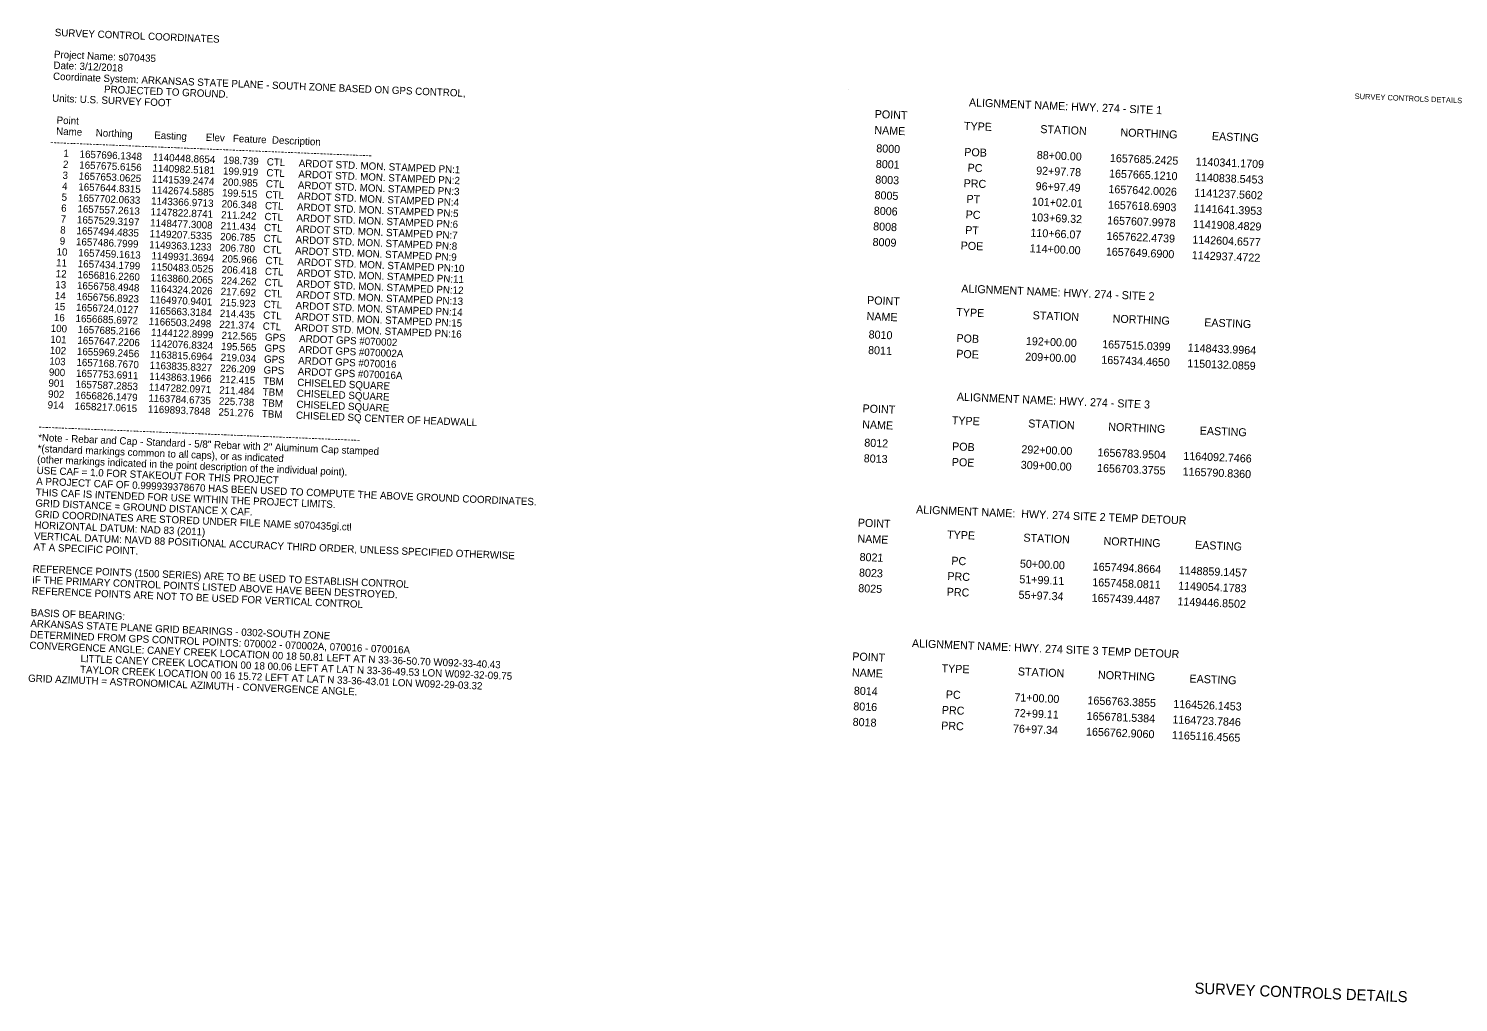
# Model space of a CAD drawing. Extents: x 1140425 to 1141974, y 1657093 to 1658148.
import ezdxf

# ---------------------------------------------------------------- set-up
doc = ezdxf.new("R2010")
doc.units = 0
for name, color, linetype in [('Default', 7, 'Continuous'), ('R_Annotation', 7, 'Continuous'), ('R_Border', 7, 'Continuous')]:
    doc.layers.add(name, color=color, linetype=linetype)

msp = doc.modelspace()

# ---------------------------------------------------------------- linework, layer by layer
at = {"layer": 'Default'}
msp.add_line((1141313, 1658081.8), (1141313, 1658081.8), dxfattribs=at)

# ---------------------------------------------------------------- texts
for s, height, p in [('SURVEY CONTROL COORDINATES ', 7.91, (1140453.1, 1658139.7)), ('Project Name: s070435 ', 7.91, (1140452.2, 1658116)), ('Date: 3/12/2018 ', 7.91, (1140451.7, 1658104.2)), ('Coordinate System: ARKANSAS STATE PLANE - SOUTH ZONE BASED ON GPS CONTROL, ', 7.91, (1140451.2, 1658092.3)), ('                   PROJECTED TO GROUND. ', 7.91, (1140450.7, 1658080.5)), ('Units: U.S. SURVEY FOOT ', 7.91, (1140450.2, 1658068.6)), ('ALIGNMENT NAME: HWY. 274 - SITE 1', 8.67, (1141443.5, 1658063.6)), ('  Point ', 7.91, (1140449.2, 1658044.9)), ('POINT', 8.67, (1141341.4, 1658050.9)), ('TYPE', 8.67, (1141438.1, 1658038.1)), ('  Name     Northing        Easting       Elev   Feature  Description ', 7.91, (1140448.7, 1658033.1)), ('NAME', 8.67, (1141341, 1658033.6)), ('STATION', 8.67, (1141520.8, 1658034.6)), ('NORTHING', 8.67, (1141607.6, 1658031.1)), ('EASTING', 8.67, (1141706.7, 1658027)), ('--------------------------------------------------------------------------------------------------- ', 7.91, (1140448.2, 1658021.2)), ('     1    1657696.1348    1140448.8654   198.739   CTL     ARDOT STD. MON. STAMPED PN:1 ', 7.91, (1140447.7, 1658009.3)), ('8000', 8.67, (1141343.1, 1658013.8)), ('POB', 8.67, (1141438.4, 1658009.9)), ('     2    1657675.6156    1140982.5181   199.919   CTL     ARDOT STD. MON. STAMPED PN:2 ', 7.91, (1140447.3, 1657997.5)), ('8001', 8.67, (1141342.6, 1657996.9)), ('PC', 8.67, (1141442, 1657992.8)), ('88+00.00', 8.67, (1141517, 1658006.6)), ('1657685.2425', 8.67, (1141596.2, 1658003.3)), ('1140341.1709', 8.67, (1141689, 1657999.5)), ('     3    1657653.0625    1141539.2474   200.985   CTL     ARDOT STD. MON. STAMPED PN:3 ', 7.91, (1140446.8, 1657985.6)), ('8003', 8.67, (1141342, 1657980)), ('PRC', 8.67, (1141437.7, 1657976)), ('92+97.78', 8.67, (1141516.3, 1657989.7)), ('1657665.1210', 8.67, (1141595.3, 1657986.5)), ('1140838.5453', 8.67, (1141688.4, 1657982.6)), ('     5    1657702.0633    1143366.9713   206.348   CTL     ARDOT STD. MON. STAMPED PN:5 ', 7.91, (1140445.8, 1657961.9)), ('     4    1657644.8315    1142674.5885   199.515   CTL     ARDOT STD. MON. STAMPED PN:4 ', 7.91, (1140446.3, 1657973.8)), ('8005', 8.67, (1141341.2, 1657963.1)), ('96+97.49', 8.67, (1141515.7, 1657972.8)), ('1657642.0026', 8.67, (1141594.6, 1657969.6)), ('1141237.5602', 8.67, (1141687.7, 1657965.7)), ('     6    1657557.2613    1147822.8741   211.242   CTL     ARDOT STD. MON. STAMPED PN:6 ', 7.91, (1140445.3, 1657950.1)), ('8006', 8.67, (1141340.4, 1657946.2)), ('PT', 8.67, (1141440.8, 1657959)), ('101+02.01', 8.67, (1141511.6, 1657956.1)), ('1657618.6903', 8.67, (1141594.1, 1657952.7)), ('1141641.3953', 8.67, (1141687, 1657948.8)), ('     7    1657529.3197    1148477.3008   211.434   CTL     ARDOT STD. MON. STAMPED PN:7 ', 7.91, (1140444.8, 1657938.2)), ('8008', 8.67, (1141339.7, 1657929.3)), ('PC', 8.67, (1141439.9, 1657942.1)), ('103+69.32', 8.67, (1141510.9, 1657939.2)), ('1657607.9978', 8.67, (1141593.2, 1657935.8)), ('1141908.4829', 8.67, (1141686.2, 1657931.9)), ('     8    1657494.4835    1149207.5335   206.785   CTL     ARDOT STD. MON. STAMPED PN:8 ', 7.91, (1140444.3, 1657926.4)), ('PT', 8.67, (1141439.4, 1657925.2)), ('110+66.07', 8.67, (1141510.1, 1657922.3)), ('1657622.4739', 8.67, (1141592.6, 1657918.9)), ('1142604.6577', 8.67, (1141685.5, 1657915)), ('    10    1657459.1613    1149931.3694   205.966   CTL     ARDOT STD. MON. STAMPED PN:10 ', 7.91, (1140443.3, 1657902.6)), ('     9    1657486.7999    1149363.1233   206.780   CTL     ARDOT STD. MON. STAMPED PN:9 ', 7.91, (1140443.8, 1657914.5)), ('8009', 8.67, (1141339.1, 1657912.4)), ('POE', 8.67, (1141434.5, 1657908.5)), ('114+00.00', 8.67, (1141509.3, 1657905.4)), ('1657649.6900', 8.67, (1141591.8, 1657902)), ('    11    1657434.1799    1150483.0525   206.418   CTL     ARDOT STD. MON. STAMPED PN:11 ', 7.91, (1140442.8, 1657890.8)), ('1142937.4722', 8.67, (1141684.9, 1657898.1)), ('    12    1656816.2260    1163860.2065   224.262   CTL     ARDOT STD. MON. STAMPED PN:12 ', 7.91, (1140442.4, 1657878.9)), ('    14    1656756.8923    1164970.9401   215.923   CTL     ARDOT STD. MON. STAMPED PN:14 ', 7.91, (1140441.4, 1657855.2)), ('    13    1656758.4948    1164324.2026   217.692   CTL     ARDOT STD. MON. STAMPED PN:13 ', 7.91, (1140441.9, 1657867.1)), ('ALIGNMENT NAME: HWY. 274 - SITE 2', 8.67, (1141435.2, 1657862)), ('    15    1656724.0127    1165663.3184   214.435   CTL     ARDOT STD. MON. STAMPED PN:15 ', 7.91, (1140440.9, 1657843.4)), ('POINT', 8.67, (1141333.1, 1657849.3)), ('TYPE', 8.67, (1141429.8, 1657836.4)), ('    16    1656685.6972    1166503.2498   221.374   CTL     ARDOT STD. MON. STAMPED PN:16 ', 7.91, (1140440.4, 1657831.5)), ('NAME', 8.67, (1141332.6, 1657832)), ('STATION', 8.67, (1141512.5, 1657833)), ('NORTHING', 8.67, (1141599.2, 1657829.4)), ('EASTING', 8.67, (1141698.4, 1657825.3)), ('   101    1657647.2206    1142076.8324   195.565   GPS     ARDOT GPS #070002A ', 7.91, (1140439.4, 1657807.8)), ('   100    1657685.2166    1144122.8999   212.565   GPS     ARDOT GPS #070002 ', 7.91, (1140439.9, 1657819.7)), ('8010', 8.67, (1141334.8, 1657812.2)), ('POB', 8.67, (1141430, 1657808.2)), ('   102    1655969.2456    1163815.6964   219.034   GPS     ARDOT GPS #070016 ', 7.91, (1140438.9, 1657795.9)), ('8011', 8.67, (1141334.2, 1657795.3)), ('POE', 8.67, (1141429.7, 1657791.3)), ('192+00.00', 8.67, (1141505.2, 1657805.1)), ('1657515.0399', 8.67, (1141587.8, 1657801.7)), ('1148433.9964', 8.67, (1141680.5, 1657797.9)), ('   103    1657168.7670    1163835.8327   226.209   GPS     ARDOT GPS #070016A ', 7.91, (1140438.4, 1657784.1)), ('209+00.00', 8.67, (1141504.5, 1657788.2)), ('1657434.4650', 8.67, (1141586.9, 1657784.8)), ('1150132.0859', 8.67, (1141680, 1657781)), ('   901    1657587.2853    1147282.0971   211.484   TBM     CHISELED SQUARE ', 7.91, (1140437.4, 1657760.4)), ('   900    1657753.6911    1143863.1966   212.415   TBM     CHISELED SQUARE ', 7.91, (1140437.9, 1657772.2)), ('   902    1656826.1479    1163784.6735   225.738   TBM     CHISELED SQUARE ', 7.91, (1140437, 1657748.5)), ('ALIGNMENT NAME: HWY. 274 - SITE 3', 8.67, (1141430.4, 1657744.8)), ('   914    1658217.0615    1169893.7848   251.276   TBM     CHISELED SQ CENTER OF HEADWALL ', 7.91, (1140436.5, 1657736.7)), ('POINT', 8.67, (1141328.2, 1657732.1)), ('NAME', 8.67, (1141327.8, 1657714.8)), ('TYPE', 8.67, (1141424.9, 1657719.2)), ('STATION', 8.67, (1141507.7, 1657715.8)), ('*Note - Rebar and Cap - Standard - 5/8" Rebar with 2" Aluminum Cap stamped ', 7.91, (1140435, 1657701.1)), ('--------------------------------------------------------------------------------------------------- ', 7.91, (1140435.5, 1657713)), ('NORTHING', 8.67, (1141594.4, 1657712.2)), ('EASTING', 8.67, (1141693.5, 1657708.1)), ('*(standard markings common to all caps), or as indicated ', 7.91, (1140434.5, 1657689.2)), ('8012', 8.67, (1141330.1, 1657695)), ('POB', 8.67, (1141425.2, 1657691)), ('292+00.00', 8.67, (1141500.3, 1657687.9)), ('1656783.9504', 8.67, (1141582.8, 1657684.5)), ('(other markings indicated in the point description of the individual point).  ', 7.91, (1140434, 1657677.4)), ('8013', 8.67, (1141329.5, 1657678.1)), ('POE', 8.67, (1141424.9, 1657674.1)), ('309+00.00', 8.67, (1141499.6, 1657671)), ('1656703.3755', 8.67, (1141582.3, 1657667.6)), ('1164092.7466', 8.67, (1141675.7, 1657680.7)), ('A PROJECT CAF OF 0.999939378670 HAS BEEN USED TO COMPUTE THE ABOVE GROUND COORDINATES. ', 7.91, (1140433, 1657653.7)), ('USE CAF = 1.0 FOR STAKEOUT FOR THIS PROJECT ', 7.91, (1140433.5, 1657665.5)), ('1165790.8360', 8.67, (1141675, 1657663.8)), ('THIS CAF IS INTENDED FOR USE WITHIN THE PROJECT LIMITS. ', 7.91, (1140432.5, 1657641.8)), ('GRID DISTANCE = GROUND DISTANCE X CAF. ', 7.91, (1140432.1, 1657630)), ('ALIGNMENT NAME:  HWY. 274 SITE 2 TEMP DETOUR', 8.67, (1141386.2, 1657622.7)), ('HORIZONTAL DATUM: NAD 83 (2011) ', 7.91, (1140431.1, 1657606.3)), ('GRID COORDINATES ARE STORED UNDER FILE NAME s070435gi.ctl', 7.91, (1140431.6, 1657618.1)), ('POINT', 8.67, (1141323.1, 1657608.4)), ('VERTICAL DATUM: NAVD 88 POSITIONAL ACCURACY THIRD ORDER, UNLESS SPECIFIED OTHERWISE  ', 7.91, (1140430.6, 1657594.4)), ('NAME', 8.67, (1141322.7, 1657591.1)), ('TYPE', 8.67, (1141419.8, 1657595.5)), ('STATION', 8.67, (1141502.5, 1657592.1)), ('AT A SPECIFIC POINT. ', 7.91, (1140430.1, 1657582.6)), ('NORTHING', 8.67, (1141589.3, 1657588.5)), ('EASTING', 8.67, (1141688.4, 1657584.4)), ('REFERENCE POINTS (1500 SERIES) ARE TO BE USED TO ESTABLISH CONTROL ', 7.91, (1140429.1, 1657558.8)), ('8021', 8.67, (1141325, 1657571.2)), ('PC', 8.67, (1141424.4, 1657567.1)), ('50+00.00', 8.67, (1141498.7, 1657564)), ('1657494.8664', 8.67, (1141577.6, 1657560.8)), ('IF THE PRIMARY CONTROL POINTS LISTED ABOVE HAVE BEEN DESTROYED. ', 7.91, (1140428.6, 1657547)), ('8023', 8.67, (1141324.4, 1657554.3)), ('PRC', 8.67, (1141420.1, 1657550.4)), ('51+99.11', 8.67, (1141498.1, 1657547.1)), ('1657458.0811', 8.67, (1141577.1, 1657543.9)), ('1148859.1457', 8.67, (1141670.7, 1657556.9)), ('REFERENCE POINTS ARE NOT TO BE USED FOR VERTICAL CONTROL ', 7.91, (1140428.1, 1657535.1)), ('8025', 8.67, (1141323.6, 1657537.4)), ('PRC', 8.67, (1141419.4, 1657533.5)), ('55+97.34', 8.67, (1141497.2, 1657530.3)), ('1657439.4487', 8.67, (1141576.4, 1657527)), ('1149054.1783', 8.67, (1141670.1, 1657540)), ('1149446.8502', 8.67, (1141669.4, 1657523.1)), ('ARKANSAS STATE PLANE GRID BEARINGS - 0302-SOUTH ZONE ', 7.91, (1140426.7, 1657499.6)), ('BASIS OF BEARING: ', 7.91, (1140427.1, 1657511.4)), ('DETERMINED FROM GPS CONTROL POINTS: 070002 - 070002A, 070016 - 070016A', 7.91, (1140426.2, 1657487.7)), ('CONVERGENCE ANGLE: CANEY CREEK LOCATION 00 18 50.81 LEFT AT N 33-36-50.70 W092-33-40.43', 7.91, (1140425.7, 1657475.9)), ('ALIGNMENT NAME: HWY. 274 SITE 3 TEMP DETOUR', 8.67, (1141381.7, 1657477.8)), ('                   TAYLOR CREEK LOCATION 00 16 15.72 LEFT AT LAT N 33-36-43.01 LON W092-29-03.32', 7.91, (1140424.7, 1657452.1)), ('                   LITTLE CANEY CREEK LOCATION 00 18 00.06 LEFT AT LAT N 33-36-49.53 LON W092-32-09.75', 7.9103, (1140425.2, 1657464)), ('POINT', 8.67, (1141317.1, 1657463.5)), ('TYPE', 8.67, (1141413.8, 1657450.6)), ('GRID AZIMUTH = ASTRONOMICAL AZIMUTH - CONVERGENCE ANGLE.', 7.91, (1140424.2, 1657440.3)), ('NAME', 8.67, (1141316.7, 1657446.2)), ('STATION', 8.67, (1141496.5, 1657447.2)), ('NORTHING', 8.67, (1141583.3, 1657443.6)), ('EASTING', 8.67, (1141682.4, 1657439.5)), ('8014', 8.67, (1141318.8, 1657426.4)), ('PC', 8.67, (1141418.4, 1657422.3)), ('71+00.00', 8.67, (1141492.7, 1657419.2)), ('8016', 8.67, (1141318.2, 1657409.5)), ('PRC', 8.67, (1141414.1, 1657405.5)), ('1656763.3855', 8.67, (1141571.9, 1657415.9)), ('1164526.1453', 8.67, (1141664.8, 1657412.1)), ('8018', 8.67, (1141317.5, 1657392.6)), ('PRC', 8.67, (1141413.4, 1657388.6)), ('72+99.11', 8.67, (1141492.1, 1657402.3)), ('1656781.5384', 8.67, (1141571, 1657399)), ('1164723.7846', 8.67, (1141663.9, 1657395.2)), ('76+97.34', 8.67, (1141491.2, 1657385.4)), ('1656762.9060', 8.67, (1141570.3, 1657382.1)), ('1165116.4565', 8.67, (1141663.4, 1657378.3))]:
    msp.add_text(s, height=height, rotation=357.6311, dxfattribs=at).set_placement(p)
at = {"layer": 'R_Annotation'}
msp.add_text('SURVEY CONTROLS DETAILS ', height=12, rotation=357.6311, dxfattribs=at).set_placement((1141687.8, 1657102.6))
at = {"layer": 'R_Border'}
msp.add_text('SURVEY CONTROLS DETAILS ', height=5.862, rotation=357.6311, dxfattribs=at).set_placement((1141861.4, 1658071.6))

doc.saveas('drawing.dxf')
